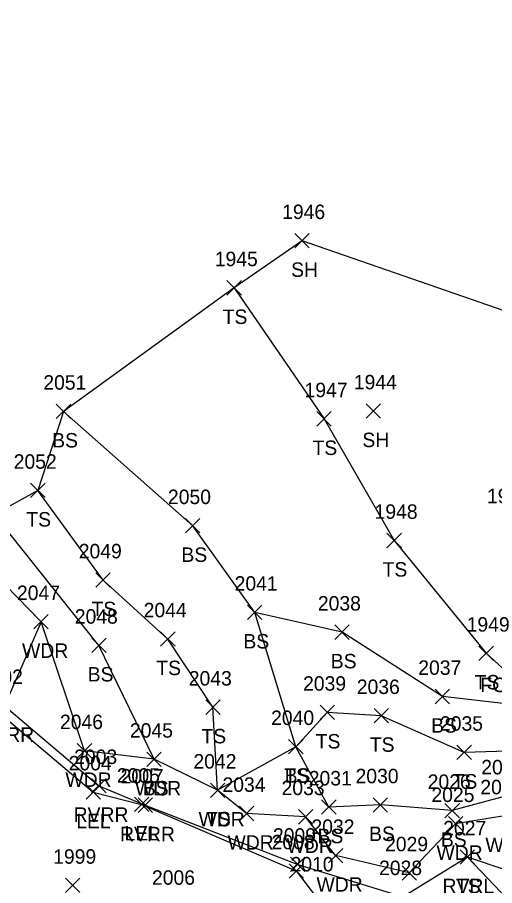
# Model space of a CAD drawing. Extents: x 1600281 to 1602254, y 862855 to 863227.
# Drawn here: x 1601927.2 to 1601993.2, y 863101.9 to 863222 of the extents above; entities that cross this region are included whole.
import ezdxf

# ---------------------------------------------------------------- set-up
doc = ezdxf.new("R2010")
doc.units = 0
for name, color, linetype in [('L_A', 7, 'Continuous'), ('L_I', 7, 'Continuous'), ('L_TIC', 7, 'Continuous'), ('LARO', 7, 'Continuous'), ('LAWA', 7, 'Continuous'), ('LAWE', 7, 'Continuous'), ('LELB', 7, 'Continuous'), ('LSOGP', 7, 'Continuous')]:
    doc.layers.add(name, color=color, linetype=linetype)

msp = doc.modelspace()

# ---------------------------------------------------------------- linework, layer by layer
at = {"layer": 'L_TIC'}
for points in [[(1601965.6, 863190.09), (1601967.6, 863192.09)], [(1601967.6, 863190.09), (1601965.6, 863192.09)], [(1601956.22, 863183.57), (1601958.22, 863185.57)], [(1601958.22, 863183.57), (1601956.22, 863185.57)], [(1601932.61, 863166.48), (1601934.61, 863168.48)], [(1601934.61, 863166.48), (1601932.61, 863168.48)], [(1601975.45, 863166.53), (1601977.45, 863168.53)], [(1601977.45, 863166.53), (1601975.45, 863168.53)], [(1601968.64, 863165.44), (1601970.64, 863167.44)], [(1601970.64, 863165.44), (1601968.64, 863167.44)], [(1601929.07, 863155.54), (1601931.07, 863157.54)], [(1601931.07, 863155.54), (1601929.07, 863157.54)], [(1601950.48, 863150.65), (1601952.48, 863152.65)], [(1601952.48, 863150.65), (1601950.48, 863152.65)], [(1601978.33, 863148.61), (1601980.33, 863150.61)], [(1601980.33, 863148.61), (1601978.33, 863150.61)], [(1601938.08, 863143.14), (1601940.08, 863145.14)], [(1601940.08, 863143.14), (1601938.08, 863145.14)], [(1601959.05, 863138.67), (1601961.05, 863140.67)], [(1601961.05, 863138.67), (1601959.05, 863140.67)], [(1601959.05, 863138.67), (1601961.05, 863140.67)], [(1601961.05, 863138.67), (1601959.05, 863140.67)], [(1601929.52, 863137.37), (1601931.52, 863139.37)], [(1601931.52, 863137.37), (1601929.52, 863139.37)], [(1601947.04, 863134.98), (1601949.04, 863136.98)], [(1601949.04, 863134.98), (1601947.04, 863136.98)], [(1601971.13, 863135.92), (1601973.13, 863137.92)], [(1601973.13, 863135.92), (1601971.13, 863137.92)], [(1601937.52, 863134.1), (1601939.52, 863136.1)], [(1601939.52, 863134.1), (1601937.52, 863136.1)], [(1601991.06, 863133), (1601993.06, 863135)], [(1601993.06, 863133), (1601991.06, 863135)], [(1601985.01, 863127.02), (1601987.01, 863129.02)], [(1601987.01, 863127.02), (1601985.01, 863129.02)], [(1601953.28, 863125.54), (1601955.28, 863127.54)], [(1601955.28, 863125.54), (1601953.28, 863127.54)], [(1601969.09, 863124.83), (1601971.09, 863126.83)], [(1601971.09, 863124.83), (1601969.09, 863126.83)], [(1601976.56, 863124.37), (1601978.56, 863126.37)], [(1601978.56, 863124.37), (1601976.56, 863126.37)], [(1601935.52, 863119.51), (1601937.52, 863121.51)], [(1601937.52, 863119.51), (1601935.52, 863121.51)], [(1601964.75, 863120.08), (1601966.75, 863122.08)], [(1601966.75, 863120.08), (1601964.75, 863122.08)], [(1601964.75, 863120.08), (1601966.75, 863122.08)], [(1601966.75, 863120.08), (1601964.75, 863122.08)], [(1601988.01, 863119.29), (1601990.01, 863121.29)], [(1601990.01, 863119.29), (1601988.01, 863121.29)], [(1601945.14, 863118.33), (1601947.14, 863120.33)], [(1601947.14, 863118.33), (1601945.14, 863120.33)], [(1601945.14, 863118.33), (1601947.14, 863120.33)], [(1601947.14, 863118.33), (1601945.14, 863120.33)], [(1601937.5, 863114.68), (1601939.5, 863116.68)], [(1601939.5, 863114.68), (1601937.5, 863116.68)], [(1601936.74, 863113.8), (1601938.74, 863115.8)], [(1601938.74, 863113.8), (1601936.74, 863115.8)], [(1601953.92, 863114.05), (1601955.92, 863116.05)], [(1601955.92, 863114.05), (1601953.92, 863116.05)], [(1601953.92, 863114.05), (1601955.92, 863116.05)], [(1601955.92, 863114.05), (1601953.92, 863116.05)], [(1601943.42, 863112.1), (1601945.42, 863114.1)], [(1601945.42, 863112.1), (1601943.42, 863114.1)], [(1601943.93, 863111.99), (1601945.93, 863113.99)], [(1601945.93, 863111.99), (1601943.93, 863113.99)], [(1601976.43, 863112.02), (1601978.43, 863114.02)], [(1601978.43, 863112.02), (1601976.43, 863114.02)], [(1601957.94, 863110.83), (1601959.94, 863112.83)], [(1601959.94, 863110.83), (1601957.94, 863112.83)], [(1601969.3, 863111.72), (1601971.3, 863113.72)], [(1601971.3, 863111.72), (1601969.3, 863113.72)], [(1601986.36, 863111.24), (1601988.36, 863113.24)], [(1601988.36, 863111.24), (1601986.36, 863113.24)], [(1601966.1, 863110.38), (1601968.1, 863112.38)], [(1601968.1, 863110.38), (1601966.1, 863112.38)], [(1601986.83, 863109.42), (1601988.83, 863111.42)], [(1601988.83, 863109.42), (1601986.83, 863111.42)], [(1601970.24, 863105.01), (1601972.24, 863107.01)], [(1601972.24, 863105.01), (1601970.24, 863107.01)], [(1601988.46, 863104.81), (1601990.46, 863106.81)], [(1601990.46, 863104.81), (1601988.46, 863106.81)], [(1601988.46, 863104.81), (1601990.46, 863106.81)], [(1601990.46, 863104.81), (1601988.46, 863106.81)], [(1601965, 863103.79), (1601967, 863105.79)], [(1601967, 863103.79), (1601965, 863105.79)], [(1601964.8, 863102.88), (1601966.8, 863104.88)], [(1601966.8, 863102.88), (1601964.8, 863104.88)], [(1601980.43, 863102.61), (1601982.43, 863104.61)], [(1601982.43, 863102.61), (1601980.43, 863104.61)], [(1601933.89, 863100.88), (1601935.89, 863102.88)], [(1601935.89, 863100.88), (1601933.89, 863102.88)]]:
    msp.add_lwpolyline(points, dxfattribs=at)
at = {"layer": 'LARO'}
msp.add_lwpolyline([(1601924.23, 863126.2), (1601937.74, 863114.8), (1601944.42, 863113.1), (1601965.8, 863103.88), (1601978.83, 863086.78)], dxfattribs=at)
at = {"layer": 'LAWA'}
msp.add_lwpolyline([(1602016.33, 863100.61), (1602006.46, 863104.44), (1601994.58, 863111.49), (1601987.83, 863110.42), (1601981.43, 863103.61), (1601971.24, 863106.01), (1601967.1, 863111.38), (1601958.94, 863111.83), (1601954.92, 863115.05), (1601946.14, 863119.33), (1601936.52, 863120.51), (1601930.52, 863138.37), (1601920.69, 863148.41)], dxfattribs=at)
at = {"layer": 'LAWE'}
for points in [[(1601925.47, 863126.75), (1601938.5, 863115.68), (1601944.93, 863112.99), (1601966, 863104.79), (1601980.59, 863100.31)], [(1602053.38, 863085.57), (1602049.01, 863088.6), (1602037.88, 863092.46), (1602027.14, 863095.15), (1602014.53, 863094.67), (1602004.69, 863100.66), (1601989.46, 863105.81), (1601980.59, 863100.31)]]:
    msp.add_lwpolyline(points, dxfattribs=at)
at = {"layer": 'LELB'}
for points in [[(1601957.22, 863184.57), (1601969.64, 863166.44), (1601979.33, 863149.61), (1601992.06, 863134), (1602000.4, 863126.37)], [(1602000.4, 863126.37), (1601986.01, 863128.02), (1601972.13, 863136.92), (1601960.05, 863139.67), (1601951.48, 863151.65), (1601933.61, 863167.48)], [(1602009.21, 863121.65), (1602004.05, 863120.74), (1601989.01, 863120.29), (1601977.56, 863125.37), (1601970.09, 863125.83), (1601965.75, 863121.08), (1601954.92, 863115.05), (1601954.28, 863126.54), (1601948.04, 863135.98), (1601939.08, 863144.14), (1601930.07, 863156.54)], [(1601946.14, 863119.33), (1601938.52, 863135.1), (1601924.03, 863153.21)], [(1602035.27, 863100.33), (1602024.88, 863102.89), (1602020.24, 863102.93), (1602006.78, 863113.18), (1601994.72, 863114.25), (1601987.36, 863112.24), (1601977.43, 863113.02), (1601970.3, 863112.72), (1601965.75, 863121.08), (1601960.05, 863139.67)], [(1602014.53, 863094.67), (1602005.53, 863091.7), (1601996.85, 863098.02), (1601989.46, 863105.81)]]:
    msp.add_lwpolyline(points, dxfattribs=at)
at = {"layer": 'LSOGP'}
for points in [[(1602125.54, 863173.4), (1602109.27, 863175.06), (1602106.49, 863191.71), (1602074.27, 863197.4), (1602065.05, 863222), (1602049.13, 863212.71), (1602032.11, 863201.55), (1602028.2, 863197), (1602026.67, 863194.3), (1602025.94, 863190.59), (1602025.23, 863186.89), (1602007.36, 863182.61), (1601999.34, 863179.73), (1601966.6, 863191.09), (1601957.22, 863184.57), (1601933.61, 863167.48), (1601930.07, 863156.54), (1601924.03, 863153.21)], [(1601920.69, 863148.41), (1601930.52, 863138.37), (1601925.47, 863126.75)]]:
    msp.add_lwpolyline(points, dxfattribs=at)

# ---------------------------------------------------------------- texts
at = {"layer": 'L_A'}
for s, p in [('SH', (1601965.09, 863186.09)), ('TS', (1601955.63, 863179.57)), ('BS', (1601932.05, 863162.48)), ('SH', (1601974.94, 863162.53)), ('TS', (1601968.05, 863161.44)), ('TS', (1601928.48, 863151.54)), ('BS', (1601949.92, 863146.65)), ('TS', (1601977.74, 863144.61)), ('TS', (1601937.49, 863139.14)), ('BS', (1601958.49, 863134.67)), ('BS', (1601958.49, 863134.67)), ('WDR', (1601927.89, 863133.37)), ('BS', (1601970.57, 863131.92)), ('BS', (1601936.96, 863130.1)), ('TS', (1601946.45, 863130.98)), ('TS', (1601990.47, 863129)), ('FOUNDATION', (1601991.26, 863128.63)), ('BS', (1601984.45, 863123.02)), ('RVRR', (1601921.98, 863121.75)), ('TS', (1601952.69, 863121.54)), ('TS', (1601968.49, 863120.83)), ('TS', (1601975.97, 863120.37)), ('TS', (1601964.16, 863116.08)), ('BS', (1601964.19, 863116.08)), ('WDR', (1601933.88, 863115.51)), ('WDR', (1601943.5, 863114.33)), ('BS', (1601944.58, 863114.33)), ('TS', (1601987.42, 863115.29)), ('RVRR', (1601935.02, 863110.68)), ('LEL', (1601935.38, 863109.8)), ('WDR', (1601952.29, 863110.05)), ('TS', (1601953.33, 863110.05)), ('RVRR', (1601941.44, 863107.99)), ('LEL', (1601942.06, 863108.1)), ('BS', (1601968.74, 863107.72)), ('BS', (1601975.87, 863108.02)), ('BS', (1601985.8, 863107.24)), ('WDR', (1601956.3, 863106.83)), ('WDR', (1601964.47, 863106.38)), ('WDR', (1601991.95, 863106.49)), ('WDR', (1601985.19, 863105.42)), ('WDR', (1601968.6, 863101.01)), ('RVRL', (1601986.03, 863100.81)), ('TS', (1601987.87, 863100.81))]:
    msp.add_text(s, height=2, dxfattribs=at).set_placement(p)
at = {"layer": 'L_I'}
for s, p in [('1946', (1601963.85, 863194.09)), ('1945', (1601954.53, 863187.57)), ('2051', (1601930.83, 863170.48)), ('1944', (1601973.76, 863170.53)), ('1947', (1601966.95, 863169.44)), ('2052', (1601926.73, 863159.54)), ('2050', (1601948.06, 863154.65)), ('1943', (1601992.17, 863154.77)), ('1948', (1601976.63, 863152.61)), ('2049', (1601935.73, 863147.14)), ('2041', (1601957.28, 863142.67)), ('2041', (1601957.28, 863142.67)), ('2047', (1601927.18, 863141.37)), ('2038', (1601968.79, 863139.92)), ('2044', (1601944.7, 863138.98)), ('2048', (1601935.18, 863138.1)), ('1949', (1601989.36, 863137)), ('2037', (1601982.67, 863131.02)), ('2002', (1601922.05, 863129.75)), ('2043', (1601950.94, 863129.54)), ('2039', (1601966.74, 863128.83)), ('2036', (1601974.17, 863128.37)), ('2040', (1601962.32, 863124.08)), ('2040', (1601962.32, 863124.08)), ('2046', (1601933.13, 863123.51)), ('2035', (1601985.67, 863123.29)), ('2045', (1601942.8, 863122.33)), ('2045', (1601942.8, 863122.33)), ('2003', (1601935.09, 863118.68)), ('2042', (1601951.58, 863118.05)), ('2042', (1601951.58, 863118.05)), ('2004', (1601934.33, 863117.8)), ('2023', (1601991.38, 863117.25)), ('2005', (1601941, 863116.1)), ('2007', (1601941.51, 863115.99)), ('2031', (1601967.53, 863115.72)), ('2030', (1601974, 863116.02)), ('2034', (1601955.6, 863114.83)), ('2033', (1601963.77, 863114.38)), ('2026', (1601983.97, 863115.24)), ('2024', (1601991.25, 863114.49)), ('2025', (1601984.49, 863113.42)), ('2032', (1601967.9, 863109.01)), ('2027', (1601986.12, 863108.81)), ('2027', (1601986.12, 863108.81)), ('2009', (1601962.58, 863107.79)), ('2008', (1601962.39, 863106.88)), ('2029', (1601978.08, 863106.61)), ('1999', (1601932.19, 863104.88)), ('2010', (1601965.01, 863103.82)), ('2028', (1601977.25, 863103.31)), ('2028', (1601977.25, 863103.31)), ('2006', (1601945.85, 863101.97))]:
    msp.add_text(s, height=2, dxfattribs=at).set_placement(p)

doc.saveas('drawing.dxf')
